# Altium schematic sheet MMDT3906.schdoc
size 127 x 101 mm
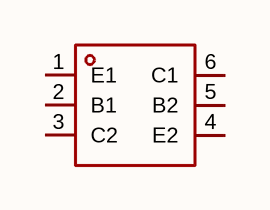
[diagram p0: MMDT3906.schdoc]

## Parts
Q?  mmdt3906_c20534  [SOT-363_L2.0-W1.3-P0.65-LS2.1-BL]  (value not drawn)

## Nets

Not connected (* = marked no-connect by the designer): Q? 1(E1) 2(B1) 3(C2) 4(E2) 5(B2) 6(C1)

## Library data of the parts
Q? = mmdt3906_c20534: 晶体管类型:PNP;集电极电流(Ic):200mA;集射极击穿电压(Vceo):40V;耗散功率(Pd):200mW;直流电流增益(hFE):60;; Manufacturer: CJ(江苏长电/长晶); AddInBom: yes; ModelId: ea15c7b026c54341854a7f0d9614aed9; ModelName: SOT-363-6P_L2.0-W1.3-H1.1-LS2.0-P0.65; ModelTransform: 83.17133,78.74,0,90,0,0,0,0,0; type: PNP; Current - Collector(Ic): 200mA; Collector - Emitter Voltage VCEO: 40V; Pd - Power Dissipation: 200mW; DC Current Gain: 60; Transition frequency(fT): 250MHz; Current - Collector Cutoff: 50nA; Vce Saturation(VCE(sat)): 400mV; Emitter-Base Voltage(Vebo): 5V; Number: 2个PNP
